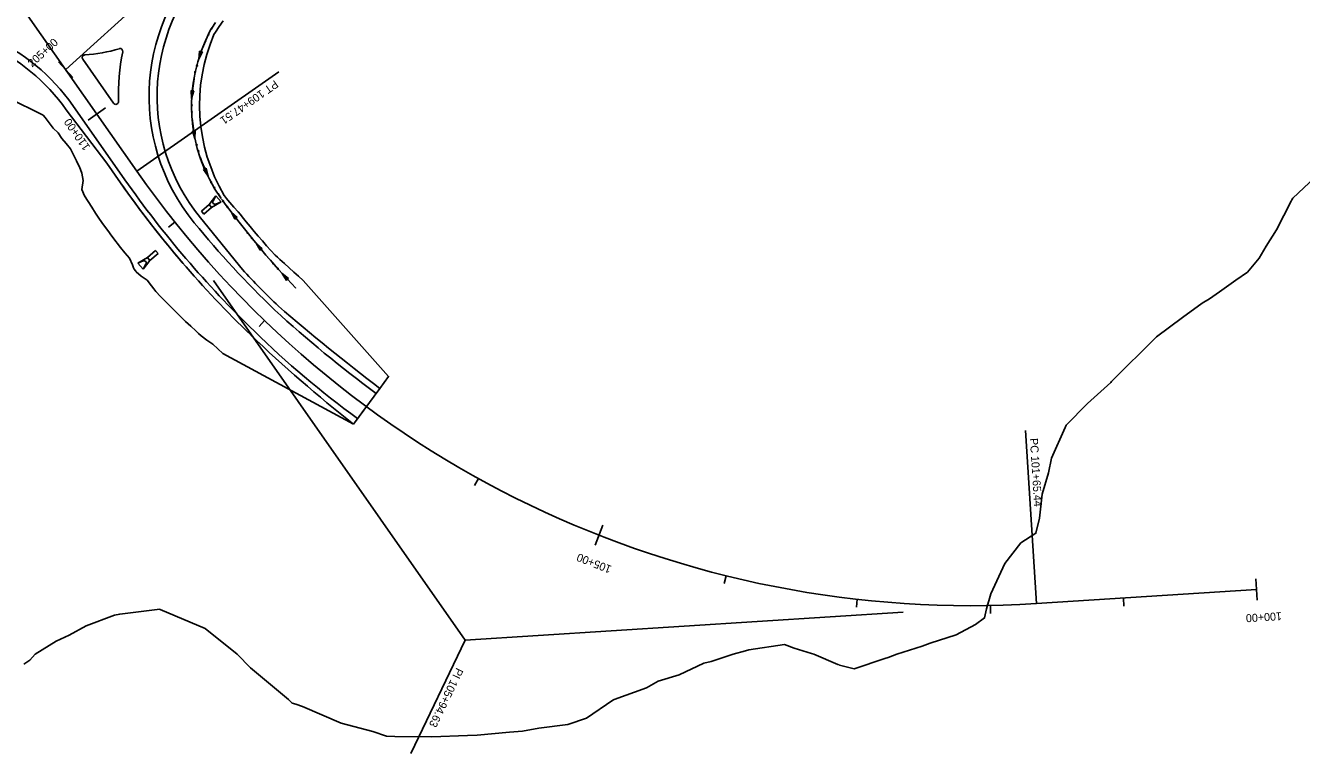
# Model space of a CAD drawing. Extents: x 916431 to 921570, y 1763982 to 1768032.
# Drawn here: x 919470 to 920427, y 1763982 to 1764528 of the extents above; entities that cross this region are included whole.
import ezdxf

# ---------------------------------------------------------------- set-up
doc = ezdxf.new("R2010")
doc.units = 0
for name, color, linetype in [('43', 7, 'Continuous'), ('R_Drainage', 7, 'Continuous'), ('R_Horz Alg', 7, 'Continuous'), ('R_Horz Alg Annot', 7, 'Continuous'), ('R_Horz Alg Stationing', 7, 'Continuous'), ('R_Proposed Const Limits', 7, 'Continuous'), ('R_Proposed Road', 7, 'Continuous'), ('R_SFHA', 7, 'Continuous'), ('R_Shld', 7, 'Continuous'), ('R_Special Ditch', 7, 'Continuous')]:
    doc.layers.add(name, color=color, linetype=linetype)

# ---------------------------------------------------------------- blocks, each defined once
blk = doc.blocks.new('36F_PL')
at = {"layer": '43'}
for p, q in [((0, 0), (-0.15, -0.815)), ((0, 0), (0.3, 0)), ((0.45, -0.815), (0.3, 0)), ((-0.007, -0.402), (-0.15, -0.815)), ((-0.15, -0.815), (0.45, -0.815)), ((0.308, -0.402), (0.45, -0.815))]:
    blk.add_line(p, q, dxfattribs=at)
blk.add_arc((0.15, -0.456), 0.167, 19.04262, 160.95738, dxfattribs=at)

msp = doc.modelspace()

# ---------------------------------------------------------------- linework, layer by layer
at = {"layer": 'R_Drainage'}
for p, q in [((919601.97, 1764389.04), (919607.7, 1764393.97)), ((919601.97, 1764389.04), (919603.93, 1764386.77)), ((919603.93, 1764386.77), (919609.65, 1764391.69)), ((919561.45, 1764354.2), (919567.58, 1764359.46)), ((919561.45, 1764354.2), (919563.41, 1764351.92)), ((919563.41, 1764351.92), (919569.54, 1764357.19)), ((919567.58, 1764359.46), (919569.54, 1764357.19))]:
    msp.add_line(p, q, dxfattribs=at)
at = {"layer": 'R_Horz Alg'}
for p, q in [((919553.63, 1764418.82), (919407.55, 1764627.45)), ((919500.23, 1764495.09), (919615.38, 1764599.5)), ((920393.22, 1764105.15), (920228.12, 1764094.6))]:
    msp.add_line(p, q, dxfattribs=at)
msp.add_arc((920179.42, 1764856.99), 763.94, 214.99917, 273.65472, dxfattribs=at)
at = {"layer": 'R_Horz Alg Annot'}
for q in [(919610.98, 1764336.91), (920128.32, 1764088.23)]:
    msp.add_line((919799.8, 1764067.25), q, dxfattribs=at)
for points in [[(919553.63, 1764418.82), (919660.12, 1764493.39)], [(920228.12, 1764094.6), (920219.83, 1764224.34)], [(919799.8, 1764067.25), (919758.93, 1763982.24)]]:
    msp.add_lwpolyline(points, dxfattribs=at)
at = {"layer": 'R_Horz Alg Stationing'}
for points in [[(919494.85, 1764501.01), (919505.6, 1764489.16)], [(919516.97, 1764457.23), (919530.08, 1764466.41)], [(919577.38, 1764377.03), (919582.07, 1764380.77)], [(919645.18, 1764302.56), (919649.34, 1764306.88)], [(919722.12, 1764237.57), (919725.68, 1764242.39)], [(919806.88, 1764183.18), (919809.78, 1764188.43)], [(919897.29, 1764138.45), (919903.13, 1764153.35)], [(919993.97, 1764109.72), (919995.42, 1764115.54)], [(920393.73, 1764097.17), (920392.71, 1764113.13)], [(920093.1, 1764091.9), (920093.77, 1764097.87)], [(920293.81, 1764092.79), (920293.42, 1764098.77)], [(920193.7, 1764087.18), (920193.59, 1764093.18)]]:
    msp.add_lwpolyline(points, dxfattribs=at)
at = {"layer": 'R_Proposed Const Limits'}
for points in [[(919611.35, 1764521.4), (919612.49, 1764523.17), (919615.36, 1764527.45), (919618.35, 1764531.59)], [(919395.2, 1764501.09), (919398.73, 1764496.71), (919402.68, 1764496.08), (919406.65, 1764495.3), (919410.58, 1764494.14), (919414.56, 1764493.01), (919418.55, 1764491.71), (919422.57, 1764490.26), (919426.61, 1764488.64), (919430.67, 1764486.82), (919483.34, 1764460.92)], [(919494.5, 1764447.6), (919490.79, 1764451.11), (919487.76, 1764455.09), (919484.74, 1764459.08), (919483.34, 1764460.92)], [(919716.02, 1764229.31), (919618.15, 1764282.09), (919614.22, 1764285.59), (919610.47, 1764289.28), (919605.95, 1764292.21), (919601.77, 1764295.49), (919599.82, 1764297.29), (919597.89, 1764299.08), (919593.95, 1764302.61), (919590.16, 1764306.29), (919586.36, 1764309.97), (919582.54, 1764313.63), (919578.89, 1764317.46), (919575.13, 1764321.18), (919571.44, 1764324.98), (919567.8, 1764328.82), (919566.32, 1764330.69), (919564.53, 1764332.98), (919561.28, 1764337.16), (919556.8, 1764340.31), (919553.12, 1764343.49), (919552.79, 1764343.87), (919552.47, 1764344.24), (919551.6, 1764345.34), (919551.6, 1764345.34), (919551.51, 1764345.56), (919551.39, 1764345.86), (919551.15, 1764346.51), (919550.36, 1764348.72), (919548.16, 1764353.74), (919544.55, 1764357.62), (919541.24, 1764361.74), (919538.78, 1764364.85), (919537.99, 1764365.91), (919534.92, 1764370.22), (919531.75, 1764374.45), (919528.58, 1764378.69), (919525.6, 1764383.05), (919522.69, 1764387.47), (919519.84, 1764391.92), (919517.09, 1764396.28), (919514.43, 1764400.51), (919512.33, 1764405.15), (919513.22, 1764411.88), (919512.43, 1764417.43), (919510.63, 1764422.27), (919509.44, 1764424.5), (919508.24, 1764426.7), (919506.03, 1764431.26), (919503.78, 1764435.79), (919500.51, 1764439.6), (919497.22, 1764443.4), (919494.5, 1764447.6)], [(919678.28, 1764336.91), (919674.78, 1764340.09), (919671.27, 1764343.27), (919667.78, 1764346.47), (919664.25, 1764349.63), (919660.72, 1764352.8), (919658.96, 1764354.4), (919657.23, 1764356.01), (919654, 1764359.48), (919650.87, 1764363.03), (919647.75, 1764366.6), (919644.67, 1764370.19), (919641.58, 1764373.78), (919638.52, 1764377.39), (919635.5, 1764381.03), (919632.54, 1764384.73), (919631.22, 1764386.4), (919629.61, 1764388.45), (919626.32, 1764391.86), (919623.26, 1764395.46), (919620.58, 1764398.8), (919620.3, 1764399.15), (919620.04, 1764399.5), (919619.26, 1764400.48), (919619.25, 1764400.48), (919619.13, 1764400.64)], [(919678.28, 1764336.91), (919742.36, 1764264.99), (919735.77, 1764256.06)]]:
    msp.add_lwpolyline(points, dxfattribs=at)
msp.add_arc((919734.71, 1764468.71), 134.14, 156.86982, 210.49394, dxfattribs=at)
at = {"layer": 'R_Proposed Road'}
for p, q in [((919536.17, 1764469.9), (919512.99, 1764503.01)), ((919505.57, 1764468.27), (919544.62, 1764412.51)), ((919735.77, 1764256.06), (919716.02, 1764229.31))]:
    msp.add_line(p, q, dxfattribs=at)
for centre, radius, start, end in [((919712.76, 1764475.19), 150, 132.19861, 219.28883), ((919382.7, 1764382.24), 150, 34.99917, 96.7925), ((919508.53, 1764613.98), 108, 273.1778, 287.18683), ((919712.76, 1764475.19), 173, 168.89589, 181.3565), ((919541.04, 1764508.9), 2, 348.89589, 107.18683), ((919514.63, 1764504.15), 2, 93.1778, 214.99917), ((919537.81, 1764471.05), 2, 214.99917, 1.3565), ((920179.42, 1764856.99), 774.94, 214.99917, 226.06275), ((920179.42, 1764856.99), 752.94, 219.28883, 226.06275), ((920301.25, 1765020.23), 955.36, 227.59439, 233.49923), ((920117.05, 1764782.41), 678, 225.48479, 234.05951)]:
    msp.add_arc(centre, radius, start, end, dxfattribs=at)
at = {"layer": 'R_SFHA'}
msp.add_lwpolyline([(919468.79, 1764049.34), (919473.26, 1764052.21), (919477.23, 1764056.67), (919492.97, 1764066.48), (919502.8, 1764070.87), (919515.55, 1764077.85), (919536.77, 1764085.94), (919540.7, 1764086.74), (919570.76, 1764090.45), (919571.16, 1764090.26), (919604.76, 1764075.86), (919628.79, 1764056.65), (919638.73, 1764046.58), (919667.38, 1764022.66), (919670.09, 1764020.07), (919672.72, 1764019.12), (919677.79, 1764017.59), (919706.73, 1764005.02), (919730.57, 1763998.8), (919740.7, 1763995.26), (919747.05, 1763995.06), (919774.67, 1763994.64), (919801.55, 1763995.77), (919808.67, 1763995.98), (919833.12, 1763998.24), (919842.65, 1763999.09), (919855.08, 1764001.13), (919876.64, 1764004.03), (919890.69, 1764008.61), (919910.6, 1764022.33), (919911.52, 1764022.69), (919935.75, 1764031.53), (919944.61, 1764036.36), (919960.14, 1764041.11), (919978.62, 1764050.09), (919984.17, 1764051.12), (920000.68, 1764056.64), (920009.97, 1764059.27), (920012.57, 1764060.09), (920039.33, 1764063.9), (920046.57, 1764061.25), (920059.6, 1764057.18), (920061.32, 1764056.67), (920079.23, 1764049.06), (920080.24, 1764048.62), (920080.55, 1764048.43), (920091.45, 1764045.8), (920114.54, 1764053.44), (920117.05, 1764054.14), (920123.54, 1764056.68), (920142.39, 1764062.78), (920148.52, 1764064.96), (920167.98, 1764071.19), (920182.53, 1764078.93), (920189.26, 1764083.91), (920190.72, 1764090.67), (920193.86, 1764101.97), (920204.47, 1764124.66), (920216.52, 1764140.12), (920227.71, 1764147.43), (920230.34, 1764158.62), (920232.35, 1764176.78), (920237.08, 1764192.64), (920239.45, 1764203.65), (920249.61, 1764226.59), (920249.88, 1764227.19), (920250.5, 1764228.41), (920266.48, 1764244.62), (920283.82, 1764260.57), (920284.49, 1764261.29), (920318.29, 1764294.72), (920337.8, 1764309.24), (920352.44, 1764319.98), (920357.82, 1764323.2), (920365.52, 1764328.54), (920377.79, 1764337.23), (920386.46, 1764343.22), (920395.29, 1764353.66), (920400.54, 1764362.57), (920408.13, 1764374.86), (920419.13, 1764396.56), (920419.65, 1764397.34), (920420.43, 1764398.74), (920436.86, 1764414.09)], dxfattribs=at)
at = {"layer": 'R_Shld'}
for p, q in [((919500.66, 1764464.83), (919530.98, 1764425.02)), ((919530.98, 1764425.02), (919541.34, 1764410.22)), ((919601.31, 1764384.01), (919632.69, 1764345.13))]:
    msp.add_line(p, q, dxfattribs=at)
for centre, radius, start, end in [((919712.76, 1764475.19), 144, 132.19861, 219.28883), ((919382.7, 1764382.24), 144, 34.99917, 96.7925), ((920179.42, 1764856.99), 778.94, 214.99917, 220.644), ((920179.42, 1764856.99), 778.94, 214.99917, 226.06275), ((920179.42, 1764856.99), 748.94, 223.11394, 226.06275), ((920752.56, 1765588.25), 1675.89, 229.30145, 232.64747), ((920389.8, 1765085.03), 1089.15, 226.41716, 231.78397)]:
    msp.add_arc(centre, radius, start, end, dxfattribs=at)
at = {"layer": 'R_Special Ditch'}
for p, q in [((919600.66, 1764508.89), (919600.03, 1764502.83)), ((919600.03, 1764502.83), (919602.7, 1764508.31)), ((919602.7, 1764508.31), (919600.66, 1764508.89)), ((919596.34, 1764479.18), (919594.24, 1764479.47)), ((919594.24, 1764479.47), (919594.48, 1764473.38)), ((919594.48, 1764473.38), (919596.34, 1764479.18)), ((919597.34, 1764449.58), (919595.25, 1764449.27)), ((919595.25, 1764449.27), (919597.18, 1764443.49)), ((919597.18, 1764443.49), (919597.34, 1764449.58)), ((919605.54, 1764421.13), (919603.62, 1764420.24)), ((919603.62, 1764420.24), (919607.08, 1764415.23)), ((919607.08, 1764415.23), (919605.54, 1764421.13)), ((919624.27, 1764388.45), (919627.07, 1764383.04)), ((919628.75, 1764384.32), (919624.27, 1764388.45)), ((919627.07, 1764383.04), (919628.75, 1764384.32)), ((919642.93, 1764364.91), (919645.97, 1764359.63)), ((919647.59, 1764360.99), (919642.93, 1764364.91)), ((919645.97, 1764359.63), (919647.59, 1764360.99)), ((919662.58, 1764342.2), (919665.85, 1764337.06)), ((919667.41, 1764338.48), (919662.58, 1764342.2)), ((919665.85, 1764337.06), (919667.41, 1764338.48))]:
    msp.add_line(p, q, dxfattribs=at)
for points in [[(919612.59, 1764530.5), (919609.77, 1764526.17), (919608.67, 1764524.37)], [(919605.31, 1764516.83), (919601.76, 1764508.88), (919600.03, 1764502.83)], [(919605.32, 1764516.87), (919605.31, 1764516.83)], [(919596.51, 1764488.24), (919594.81, 1764475.79), (919594.82, 1764473.36)], [(919596.52, 1764488.28), (919596.51, 1764488.24)], [(919594.97, 1764458.36), (919594.98, 1764458.33)], [(919594.98, 1764458.33), (919597.18, 1764443.49)], [(919601.25, 1764429.07), (919601.26, 1764429.03)], [(919601.26, 1764429.03), (919602.22, 1764425.82), (919607.08, 1764415.23)], [(919614.45, 1764402.2), (919614.47, 1764402.17)], [(919614.47, 1764402.17), (919616.79, 1764398.47)], [(919672.76, 1764331.19), (919672.76, 1764331.19), (919672.73, 1764331.22), (919669.49, 1764334.68), (919666.25, 1764338.19), (919663.02, 1764341.72), (919659.82, 1764345.27), (919656.65, 1764348.84), (919655.06, 1764350.64), (919653.75, 1764352.15), (919653.5, 1764352.43), (919650.39, 1764356.05), (919647.3, 1764359.69), (919644.23, 1764363.35), (919641.19, 1764367.03), (919638.18, 1764370.72), (919635.19, 1764374.44), (919632.23, 1764378.17), (919629.29, 1764381.92), (919627.98, 1764383.62), (919626.38, 1764385.69), (919623.49, 1764389.48), (919620.63, 1764393.28), (919618.07, 1764396.74), (919617.8, 1764397.1), (919617.54, 1764397.45), (919617.51, 1764397.49), (919617.11, 1764398.04)], [(919633.47, 1764376.61), (919632.23, 1764378.17), (919629.29, 1764381.92), (919627.98, 1764383.62), (919626.38, 1764385.69), (919624.27, 1764388.45)], [(919633.49, 1764376.58), (919633.47, 1764376.6)], [(919652.62, 1764353.46), (919650.39, 1764356.05), (919647.3, 1764359.69), (919644.23, 1764363.35), (919642.94, 1764364.92)], [(919652.64, 1764353.43), (919652.62, 1764353.46)], [(919672.76, 1764331.19), (919672.76, 1764331.19), (919672.73, 1764331.22), (919669.49, 1764334.68), (919666.25, 1764338.19), (919663.02, 1764341.72), (919662.58, 1764342.2)]]:
    msp.add_lwpolyline(points, dxfattribs=at)
for centre in [(919607.38, 1764521.41), (919609.62, 1764525.87), (919598.69, 1764498.01), (919597.32, 1764493.19), (919594.89, 1764468.35), (919594.91, 1764463.34), (919598.44, 1764438.66), (919599.87, 1764433.85), (919609.2, 1764410.7), (919611.83, 1764406.44), (919618.24, 1764396.45), (919621.23, 1764392.43), (919636.58, 1764372.66), (919639.73, 1764368.77), (919655.89, 1764349.65), (919659.21, 1764345.9)]:
    msp.add_circle(centre, 0.375, dxfattribs=at)
msp.add_arc((919714.29, 1764467.97), 119.73, 151.90128, 215.48217, dxfattribs=at)

# ---------------------------------------------------------------- block references
at = {"layer": 'R_Drainage', "xscale": 10, "yscale": 10}
for p, rotation in [((919609.65, 1764391.69), 130.69686065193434), ((919561.45, 1764354.2), -49.30313934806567)]:
    msp.add_blockref('36F_PL', p, dxfattribs=dict(at, rotation=rotation))

# ---------------------------------------------------------------- texts
at = {"layer": 'R_Horz Alg Annot'}
for s, rotation, p in [('PT 109+47.51', 214.99917, (919656.92, 1764487.49)), ('PC 101+65.44', 273.65472, (920223.21, 1764218.54)), ('PI 105+94.63', 244.32694, (919793.27, 1764046.99))]:
    msp.add_text(s, height=6, rotation=rotation, dxfattribs=at).set_placement(p)
at = {"layer": 'R_Horz Alg Stationing'}
for s, rotation, p in [('205+00', 42.19861, (919475.06, 1764496.57)), ('110+00', 124.99917, (919518.9, 1764437.04)), ('105+00', 158.56275, (919910.06, 1764122.7)), ('100+00', 183.65472, (920411.98, 1764088.31))]:
    msp.add_text(s, height=6, rotation=rotation, dxfattribs=at).set_placement(p)

doc.saveas('drawing.dxf')
